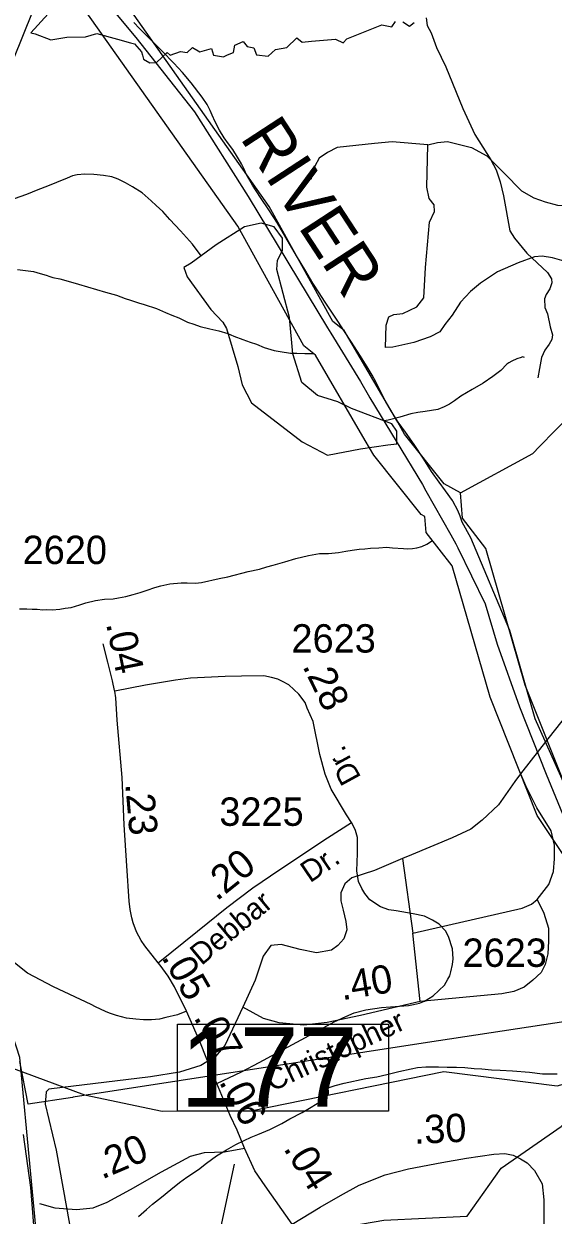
# Model space of a CAD drawing. Extents: x 2169602 to 2449496, y 721995 to 810662.
# Drawn here: x 2407514 to 2409846, y 768814 to 774064 of the extents above; entities that cross this region are included whole.
import ezdxf

# ---------------------------------------------------------------- set-up
doc = ezdxf.new("R2010")
doc.units = 0
doc.layers.add('Default', color=7, linetype='Continuous')

msp = doc.modelspace()

# ---------------------------------------------------------------- linework, layer by layer
at = {"layer": 'Default'}
for p, q in [((2409182, 770385.4), (2409227.4, 770056.2)), ((2409259.5, 769754.9), (2409227.4, 770056.2)), ((2407856.9, 766350.4), (2408442.4, 769038.3))]:
    msp.add_line(p, q, dxfattribs=at)
for points in [[(2407243.1, 773459.7), (2407266.6, 773555.6), (2407423.7, 773798.3), (2407554.7, 774123.7), (2407644.7, 774522.1), (2407675.7, 774915.1), (2407671.8, 775505.6), (2407762.6, 775631.7), (2407953.7, 775782), (2407976.7, 776132.5), (2408034.7, 776259.2), (2408241.6, 776425.6), (2408257.8, 776467.9)], [(2409161, 772308.5), (2408925.5, 772712.8), (2408875.4, 772752.6), (2408595.1, 773259.7), (2407918.3, 774218.5), (2407710.1, 774460.6), (2406974, 775062.6), (2406534.7, 775369.4), (2406337, 775427.8), (2406132.7, 775395.7), (2405988.4, 775292.7), (2405904.8, 775165.6), (2405866.1, 774953.6), (2405813.5, 774896.3), (2405664.8, 774846.1), (2405048.7, 774841.7), (2404832.6, 774882.2), (2404654.8, 774858.8), (2404509.3, 774858.8), (2404436.5, 774918.8), (2404333.7, 775051.5), (2404091.1, 775489.6), (2403987, 775680.8), (2403920.6, 775917.1)], [(2409017.8, 772228.4), (2408799.3, 772603.5), (2408747.7, 772644.5), (2408455.9, 773172.5), (2407788.9, 774117.5), (2407595.2, 774342.7), (2406875, 774931.7), (2406462.6, 775219.7), (2406326, 775260), (2406196.5, 775239.7), (2406108.7, 775177), (2406060.2, 775103.4), (2406019, 774877.5), (2405905.9, 774754.4), (2405688.3, 774680.8), (2404804.7, 774719.2), (2404466.4, 774709), (2404368, 774816), (2404234.3, 774963.9), (2403938.3, 775423.9), (2403840.1, 775854.6)], [(2407837.3, 774209.6), (2408006.5, 774004), (2408266.1, 773676), (2408501.7, 773303.2), (2408851.9, 772724.5), (2408866.1, 772701.4), (2408997.3, 772487.8), (2409030.9, 772429.7), (2409038.7, 772415.8), (2409270, 772034.6), (2409285, 772005.9), (2409395.5, 771811.6), (2409417.3, 771772.6), (2409425.7, 771755.2), (2409545.8, 771507.8), (2409599.8, 771329.8), (2409696.9, 771054.4), (2409815.7, 770757.6), (2409896.7, 770557.8)], [(2407665.9, 774158.4), (2407544.2, 774024.3), (2407563.7, 774019.7), (2407632.4, 773994.1), (2407702.9, 774005.5), (2407784.9, 774006.3), (2407835.9, 774022.2), (2407925.9, 773996), (2407983.9, 773980.4), (2408001.2, 773975.9), (2408032.4, 773940.3), (2408036.2, 773925.5), (2408040.7, 773908.6), (2408069.2, 773892.9), (2408098.7, 773893.6), (2408145.7, 773937.2), (2408158.2, 773925.6), (2408204.2, 773941.9), (2408233.9, 773937.6), (2408257.2, 773959.8), (2408288.9, 773941.1), (2408340.7, 773955.9), (2408348.7, 773925.9), (2408392.9, 773919.3), (2408411.2, 773927.1), (2408437.7, 773938.4), (2408443.2, 773969.8), (2408479.9, 773985.9), (2408497.7, 773964.3), (2408527.7, 773958.8), (2408538.4, 773928.2), (2408589.7, 773922.1), (2408622.2, 773951.6), (2408672.2, 773960.4), (2408716.7, 774002), (2408739.9, 773983.8), (2408780.7, 773987.5), (2408887.4, 773997.3), (2408919.9, 773979.8), (2408936.2, 773997.9), (2408959.4, 774007.2), (2409091.2, 774059.9), (2409135.2, 774051.4), (2409151.4, 774074.9)], [(2407665.9, 774158.4), (2407544.2, 774024.3), (2407563.7, 774019.7), (2407632.4, 773994.1), (2407702.9, 774005.5), (2407784.9, 774006.3), (2407835.9, 774022.2), (2407925.9, 773996), (2407983.9, 773980.4), (2408001.2, 773975.9), (2408032.4, 773940.3), (2408036.2, 773925.5), (2408040.7, 773908.6), (2408069.2, 773892.9), (2408098.7, 773893.6), (2408145.7, 773937.2), (2408158.2, 773925.6), (2408204.2, 773941.9), (2408233.9, 773937.6), (2408257.2, 773959.8), (2408288.9, 773941.1), (2408340.7, 773955.9), (2408348.7, 773925.9), (2408392.9, 773919.3), (2408411.2, 773927.1), (2408437.7, 773938.4), (2408443.2, 773969.8), (2408479.9, 773985.9), (2408497.7, 773964.3), (2408527.7, 773958.8), (2408538.4, 773928.2), (2408589.7, 773922.1), (2408622.2, 773951.6), (2408672.2, 773960.4), (2408716.7, 774002), (2408739.9, 773983.8), (2408780.7, 773987.5), (2408887.4, 773997.3), (2408919.9, 773979.8), (2408936.2, 773997.9), (2408959.4, 774007.2), (2409091.2, 774059.9), (2409135.2, 774051.4), (2409151.4, 774074.9)], [(2409930, 770637.4), (2409766.2, 771001.1), (2409655.2, 771391.1), (2409482.5, 771798.9), (2409445.2, 771867.8), (2409436, 771894.5), (2409426.5, 771919.3), (2409403.5, 771960.4), (2409402, 771962.9), (2409371.7, 772006.2), (2409343.2, 772044.1), (2409310.5, 772091.4), (2409275.5, 772145.9), (2409233.2, 772210.5), (2409195.7, 772264.4), (2409163.5, 772308.9), (2409133.2, 772355.3), (2409107.2, 772401.2), (2409083, 772447.6), (2409064, 772485.7), (2409048, 772515.7), (2409026.5, 772552.6), (2408997, 772599.7), (2408957.5, 772661.6), (2408927, 772708.1), (2408897, 772753.7), (2408868, 772797.4), (2408838.7, 772841.7), (2408814.5, 772878.5), (2408787.7, 772921.1), (2408755.7, 772974.3), (2408715.2, 773042.1), (2408667.7, 773122.6), (2408631, 773185.1), (2408593, 773245.2), (2408557, 773298.4), (2408521, 773352.9), (2408493.2, 773402.1), (2408483.7, 773423.1), (2408472.2, 773447.5), (2408455.7, 773476.8), (2408434, 773510.3), (2408415, 773535.9), (2408396.5, 773561.6), (2408375.5, 773596.1), (2408356.2, 773632), (2408343.2, 773661.6), (2408334.5, 773682.4), (2408320.7, 773708.1), (2408299.2, 773740.4), (2408251, 773804.6), (2408213, 773850.1), (2408174.5, 773891.2), (2408123.2, 773943.6), (2408069.2, 773997.9), (2408023.5, 774043.6), (2407998.5, 774069.7)], [(2409930, 770637.4), (2409766.2, 771001.1), (2409655.2, 771391.1), (2409482.5, 771798.9), (2409445.2, 771867.8), (2409436, 771894.5), (2409426.5, 771919.3), (2409403.5, 771960.4), (2409402, 771962.9), (2409371.7, 772006.2), (2409343.2, 772044.1), (2409310.5, 772091.4), (2409275.5, 772145.9), (2409233.2, 772210.5), (2409195.7, 772264.4), (2409163.5, 772308.9), (2409133.2, 772355.3), (2409107.2, 772401.2), (2409083, 772447.6), (2409064, 772485.7), (2409048, 772515.7), (2409026.5, 772552.6), (2408997, 772599.7), (2408957.5, 772661.6), (2408927, 772708.1), (2408897, 772753.7), (2408868, 772797.4), (2408838.7, 772841.7), (2408814.5, 772878.5), (2408787.7, 772921.1), (2408755.7, 772974.3), (2408715.2, 773042.1), (2408667.7, 773122.6), (2408631, 773185.1), (2408593, 773245.2), (2408557, 773298.4), (2408521, 773352.9), (2408493.2, 773402.1), (2408483.7, 773423.1), (2408472.2, 773447.5), (2408455.7, 773476.8), (2408434, 773510.3), (2408415, 773535.9), (2408396.5, 773561.6), (2408375.5, 773596.1), (2408356.2, 773632), (2408343.2, 773661.6), (2408334.5, 773682.4), (2408320.7, 773708.1), (2408299.2, 773740.4), (2408251, 773804.6), (2408213, 773850.1), (2408174.5, 773891.2), (2408123.2, 773943.6), (2408069.2, 773997.9), (2408023.5, 774043.6), (2407998.5, 774069.7)], [(2409183.7, 774072.7), (2409213.4, 774053.3), (2409233.7, 774069.9)], [(2409183.7, 774072.7), (2409213.4, 774053.3), (2409233.7, 774069.9)], [(2409285.9, 774090.9), (2409291.1, 774057.3), (2409307.9, 774025.1), (2409332.4, 773959.3), (2409372.4, 773874.1), (2409447.9, 773690.8), (2409500.8, 773575.9), (2409571.2, 773464.9), (2409594.4, 773421.1), (2409612.5, 773368.2), (2409626.7, 773306.2), (2409655.7, 773151.3), (2409675.1, 773120.3), (2409729.3, 773053.2), (2409821.5, 772968.1), (2409838.3, 772941), (2409839.6, 772922.9), (2409830.6, 772895.8), (2409815.1, 772871.3), (2409807.3, 772851.9), (2409809.9, 772814.5), (2409820.3, 772786.1), (2409832.5, 772729.3), (2409842.8, 772693.1), (2409840.3, 772672.5), (2409828.6, 772653.1), (2409809.3, 772626), (2409795.1, 772593.8), (2409786, 772544.7), (2409778.3, 772504.7)], [(2409294.1, 773531.4), (2409136, 773543.7), (2409059.4, 773536.3), (2408893.9, 773519), (2408852, 773496.8), (2408814.9, 773472.1), (2408795.2, 773437.5), (2408777.9, 773378.3)], [(2409107.6, 772637.3), (2409110.1, 772736.1), (2409122.4, 772773.1), (2409144.6, 772783), (2409184.2, 772787.9), (2409245.9, 772817.6), (2409275.5, 772857.1), (2409283, 772990.5), (2409301.5, 773190.5), (2409323.7, 773237.5), (2409321.2, 773267.1), (2409299, 773294.3), (2409289.1, 773343.7), (2409294.1, 773531.4)], [(2409294.1, 773531.4), (2409336.1, 773541.3), (2409380.5, 773546.2), (2409486.7, 773519), (2409553.4, 773482), (2409630, 773405.4), (2409706.6, 773328.9), (2409760.9, 773296.7), (2409810.3, 773279.5), (2409864.6, 773264.6), (2409926.4, 773262.2), (2410002.9, 773281.9), (2410069.6, 773294.3), (2410124, 773306.6), (2410185.7, 773311.6), (2410238.8, 773314)], [(2408294.6, 773042.1), (2408256.5, 773093.8), (2408204, 773151.7), (2408157.5, 773201.3), (2408125.7, 773237.3), (2408097.2, 773263.1), (2408075.3, 773284.7), (2408035.1, 773318.8), (2407992.8, 773346.2), (2407961.1, 773364), (2407928.9, 773379.8), (2407900.8, 773389.8), (2407864.7, 773395.6), (2407822.4, 773399.6), (2407782.7, 773401.1), (2407748.8, 773398.9), (2407728.5, 773394.7), (2407704.7, 773384.5), (2407656.8, 773364.6), (2407617.2, 773348.3), (2407574.9, 773331.9), (2407525.1, 773311.9), (2407471.2, 773293.3)], [(2409785.9, 772200.8), (2410062.6, 772482.8), (2410419.6, 772734.6), (2410494.4, 772834.8), (2410484.6, 773008.8), (2410375.5, 773152.2), (2410283.4, 773199.9), (2410241.6, 773276.3), (2410258.9, 773346.9)], [(2408360.9, 773090.4), (2408250.5, 773009.9), (2408217.9, 772989.8), (2408232.9, 772949.7), (2408338.2, 772804.5), (2408390.8, 772749.4), (2408405.9, 772721.8), (2408456.2, 772554.1), (2408476.1, 772473.9), (2408516.2, 772393.7), (2408739.6, 772221.9), (2408852, 772163.3), (2408997.4, 772190.8), (2409117.7, 772208.4), (2409157.8, 772213.4), (2409157.8, 772268.5), (2409135.3, 772301.1), (2408957.3, 772368.7), (2408897.6, 772398.9), (2408806.9, 772426.3), (2408739.2, 772483.9), (2408699.1, 772609.1), (2408684.1, 772769.4), (2408627.9, 772981.5), (2408631.5, 773022.4), (2408654, 773065), (2408654, 773120.1), (2408616.4, 773170.2), (2408558.8, 773185.2), (2408486.1, 773170.2), (2408360.9, 773090.4)], [(2410317.9, 773064.6), (2410136.3, 773017.6), (2410086.9, 772997.9), (2410035, 772990.5), (2409990.6, 772990.5), (2409953.5, 772997.9), (2409894.3, 773017.6), (2409842.4, 773032.5), (2409797.9, 773039.9), (2409763.4, 773037.4), (2409691.7, 773010.2), (2409600.3, 772970.7), (2409526.2, 772921.3), (2409481.8, 772884.3), (2409437.3, 772837.3), (2409400.3, 772780.5), (2409368.2, 772738.5), (2409345.9, 772706.4), (2409304, 772684.2), (2409232.3, 772659.5), (2409139.7, 772639.7), (2409107.6, 772637.3)], [(2407485.7, 772981.6), (2407521.1, 772977.8), (2407555.4, 772972.2), (2407585.1, 772964.5), (2407611.6, 772956.4), (2407627.6, 772950.4), (2407641.7, 772946.6), (2407671.9, 772940.9), (2407699.3, 772933), (2407753.7, 772917.1), (2407873.6, 772882), (2407921.8, 772868.2), (2407960, 772854.3), (2407983.7, 772846.6), (2408018.4, 772834.9), (2408043.8, 772827), (2408098.4, 772809.4), (2408138.1, 772791.6), (2408166.4, 772779.7), (2408196.4, 772767.8), (2408234.1, 772750), (2408262.4, 772740.4), (2408290.5, 772730.5), (2408332.5, 772720.5), (2408372.5, 772710.8), (2408412.7, 772699), (2408438.7, 772687), (2408478.9, 772673.6), (2408510.9, 772661.5), (2408538.6, 772652), (2408572.9, 772637.9), (2408616.9, 772624.4), (2408642.8, 772620.5), (2408688.9, 772612.7), (2408717, 772612.9), (2408751.2, 772610.9), (2408789.9, 772611)], [(2409720.2, 772594.3), (2409710.4, 772596.2), (2409704.6, 772594.3), (2409686.6, 772588.1), (2409664.4, 772578), (2409650.7, 772569.9), (2409642.5, 772563.9), (2409615, 772536), (2409580.8, 772509.5), (2409537.3, 772481.2), (2409489.3, 772453.2), (2409439.7, 772422.9), (2409411.6, 772402.9), (2409389.9, 772388.7), (2409365.7, 772376.6), (2409338.2, 772364.1), (2409310.3, 772360.2), (2409282, 772355.9), (2409250.2, 772351.8), (2409218.2, 772345.7), (2409170.2, 772331.4), (2409118.2, 772317), (2409101.3, 772313.9)], [(2409437.5, 771997.1), (2409366.4, 772037.6), (2409191.3, 772256.5), (2409161, 772308.5)], [(2409279.9, 771892.5), (2409264.7, 771902.1), (2409055.6, 772163.5), (2409017.8, 772228.4)], [(2409437.5, 771997.1), (2409756.4, 772170.8), (2409785.9, 772200.8)], [(2410451.8, 769576.3), (2410433.4, 769734.9), (2410163.8, 770289.2), (2409921.5, 770652.4), (2409723.2, 771150), (2409550, 771752), (2409445.9, 771885.5), (2409437.5, 771997.1)], [(2410288.9, 769557.4), (2410273.7, 769688.2), (2410021.2, 770207.4), (2409775.5, 770575.7), (2409567.8, 771096.8), (2409401.1, 771676.2), (2409286.9, 771822.6), (2409279.9, 771892.5)], [(2407787.3, 771511.8), (2407829.5, 771522.1), (2407869.1, 771528.3), (2407907.5, 771530.6), (2407931, 771534.7), (2407963.4, 771540.8), (2407995, 771549), (2408025.4, 771557.4), (2408057.1, 771567.6), (2408091, 771579.5), (2408116.6, 771587.8), (2408156.6, 771595.9), (2408206.6, 771600.1), (2408232.7, 771600.3), (2408270.6, 771598.6), (2408296.9, 771602.7), (2408374.8, 771619.3), (2408412.7, 771627.4), (2408502.7, 771649.9), (2408552.6, 771660.2), (2408584.3, 771670.4), (2408612.4, 771678.4), (2408664.1, 771692.8), (2408712.1, 771707.1), (2408767.9, 771721.4), (2408816, 771729.5), (2408855.6, 771730), (2408900.1, 771734.2), (2408931.7, 771740.4), (2408959.6, 771744.7), (2408991.8, 771748.7), (2409016, 771750.8), (2409041.8, 771752.9), (2409077.9, 771755.2), (2409111.3, 771757.4), (2409137.4, 771755.5), (2409185.8, 771751.9), (2409205.6, 771749.7), (2409225.5, 771751.9), (2409245.6, 771754.2), (2409267.4, 771760.2), (2409289.5, 771770.3), (2409314.5, 771787.2)], [(2407593.3, 768488.6), (2407969.6, 768561.8), (2408193.6, 768635.9), (2409100.5, 768791.2), (2409467.6, 768810), (2409616.6, 769020.2), (2409881.5, 769205), (2410196.5, 769523.3), (2410328.6, 769730.6), (2410592.5, 770233.6), (2410766.6, 770341.6), (2411514.6, 770644.5), (2411995.6, 771074.3), (2412234.5, 771423.7), (2412358.6, 771726.2)], [(2407493.7, 771486.5), (2407526.1, 771486.4), (2407549.8, 771484.5), (2407571.6, 771484.8), (2407597.8, 771480.9), (2407611.8, 771482.8), (2407637.8, 771481.3), (2407671.6, 771485.1), (2407695.6, 771489.6), (2407721.5, 771491.8), (2407759.6, 771503.9), (2407787.3, 771511.8)], [(2410196.8, 771469), (2410100.5, 771367.7), (2409996.8, 771286.2), (2409977, 771246.7), (2409977, 771212.1), (2409979.5, 771165.2), (2409972.1, 771120.7), (2409959.7, 771091.1), (2409940, 771061.5), (2409822.6, 770913.3), (2409702.2, 770758.2)], [(2407913.9, 771123.6), (2407913.3, 771126.4), (2407904.2, 771168.1), (2407883, 771250.7), (2407863.7, 771331.1)], [(2408956.8, 770544.9), (2408935.3, 770578.7), (2408867.3, 770691.5), (2408842, 770757.2), (2408818.4, 770843.7), (2408788.5, 770989), (2408762.3, 771048.4), (2408753.2, 771072.8), (2408726, 771109.5), (2408681.2, 771150.7), (2408653.6, 771165.2), (2408632.3, 771175.6), (2408604.7, 771183.8), (2408571.6, 771190.1), (2408472.4, 771188.8), (2408400, 771187.9), (2408309.4, 771183.8), (2408247.3, 771179.7), (2408181.7, 771171.1), (2408049.4, 771148.9), (2407913.9, 771123.6)], [(2408105.4, 769926.1), (2408047.1, 770000.5), (2408030.4, 770024.4), (2408010, 770062.3), (2407995, 770102.5), (2407988.7, 770124.1), (2407982.5, 770160.4), (2407977.4, 770197.6), (2407966.8, 770353.7), (2407955.4, 770534.5), (2407946.3, 770742.2), (2407925.4, 770994.6), (2407919, 771094.1), (2407913.9, 771123.6)], [(2409702.2, 770758.2), (2409676.9, 770725.6), (2409605.3, 770621.8), (2409532.4, 770555.1), (2409483, 770515.6), (2409401.5, 770476.1), (2409221.2, 770402), (2409182, 770385.4)], [(2409775.7, 770204.4), (2409827.6, 770271.1), (2409847.3, 770327.9), (2409852.3, 770384.7), (2409852.3, 770444), (2409837.5, 770508.2), (2409774.5, 770609.5), (2409725.1, 770705.8), (2409702.8, 770757.7)], [(2408105.4, 769926.1), (2408278.8, 770065.4), (2408408.7, 770170.2), (2408522.9, 770255.9), (2408642.1, 770337.6), (2408851.3, 770476.6), (2408956.8, 770544.9)], [(2408364.4, 769393.5), (2408472.5, 769444.8), (2408550.8, 769486.4), (2408789.3, 769616), (2408881.7, 769666), (2408932.2, 769689.9), (2408968.9, 769705.8), (2409020.2, 769719.1), (2409089, 769728.3), (2409207.8, 769738.1), (2409230.8, 769741.7), (2409256.9, 769747.4), (2409279, 769757.2), (2409316.6, 769779.7), (2409367, 769827.9), (2409382.5, 769853.6), (2409390, 769868.6), (2409395.3, 769886.3), (2409402.4, 769918.6), (2409405.1, 769943), (2409402.9, 769987.2), (2409384.3, 770042.5), (2409371.5, 770066.8), (2409344, 770096.5), (2409313.9, 770114.2), (2409279, 770131.4), (2409229, 770141.6), (2409154.2, 770154.4), (2409121.5, 770159.3), (2409085.2, 770172.5), (2409038.5, 770203.8), (2409015.4, 770231.8), (2409002.3, 770254), (2408987.6, 770284), (2408980.3, 770331.5), (2408983.3, 770407.6), (2408984.2, 770459.2), (2408983.7, 770477.7), (2408975.6, 770509), (2408958.4, 770542.5), (2408956.8, 770544.9)], [(2409182, 770385.4), (2409058.2, 770332.8), (2408959.4, 770300.7), (2408927.3, 770273.6), (2408910, 770234), (2408910, 770199.5), (2408919.9, 770157.5), (2408932.2, 770108.1), (2408937.2, 770071), (2408923.6, 770031.5), (2408896.4, 770001.9), (2408869.2, 769982.1), (2408802.6, 769969.8), (2408730.9, 769984.6), (2408647, 770006.8), (2408602.5, 770001.9), (2408567.9, 769954.9), (2408533.3, 769848.7), (2408479, 769730.2)], [(2409227.4, 770056.2), (2409709, 770167.4), (2409751, 770184.6), (2409775.7, 770204.4)], [(2409775.7, 770204.4), (2409805.3, 770145.1), (2409825.1, 770078.4), (2409825.1, 770021.6), (2409822.6, 769964.8), (2409810.3, 769917.9), (2409793, 769883.3), (2409755.9, 769848.7), (2409718.9, 769819.1), (2409672, 769799.3), (2409620.1, 769789.5), (2409259.5, 769754.9)], [(2408231, 769712.2), (2408190.1, 769696.9), (2408139.1, 769684.8), (2408111.9, 769678.2), (2408076, 769675.2), (2408040.5, 769674.9), (2408007.1, 769677), (2407965.6, 769682.1), (2407921.6, 769693.6), (2407891.3, 769704.2), (2407873.6, 769710.7), (2407829.5, 769732.1), (2407809.9, 769742), (2407644.7, 769819.6), (2407529.1, 769880.7), (2407472.2, 769926.1)], [(2408231, 769712.2), (2408177.8, 769820), (2408149.5, 769866.7), (2408114.1, 769914.9), (2408105.4, 769926.1)], [(2409259.5, 769754.9), (2408996.4, 769693.1), (2408850.7, 769663.5), (2408747, 769651.1), (2408638.3, 769661), (2408569.2, 769680.8), (2408479, 769730.2)], [(2407593.2, 768480.4), (2407495.4, 769508), (2407432.6, 769704.6)], [(2408479, 769730.2), (2408398.7, 769562.2), (2408358, 769512.8), (2408293.8, 769473.3), (2408199.9, 769443.7), (2408071.5, 769423.9), (2407624.4, 769369.6), (2407612.1, 769357.2), (2407607.1, 769302.9), (2407656.5, 769100.4), (2407714.6, 768774.3), (2407726.9, 768660.7), (2407724.4, 768591.5), (2407719.5, 768507.6), (2407703.4, 768164.3), (2407681.2, 767919.7), (2407665.2, 767670.3), (2407641.7, 767163.9), (2407655.3, 766860.1), (2407657.8, 766578.6), (2407693.6, 766279.7), (2407705.9, 766188.3), (2407733.1, 766096.9), (2407803.5, 765919.1)], [(2408364.4, 769393.5), (2408320.3, 769501.9), (2408288.8, 769579.3), (2408231, 769712.2)], [(2405398.5, 767831.3), (2405736.4, 768441.1), (2406472.5, 769564.4), (2406605.4, 769630.5), (2407113.5, 769590.7), (2407781.4, 769344.2), (2408123.4, 769271.5), (2408514.4, 769273.4), (2409363.5, 769446.4), (2409863.4, 769383.7), (2410304.2, 769504.3)], [(2409920.2, 769670.6), (2409273.7, 769571.1), (2407949.7, 769367.1), (2407730.7, 769333.4), (2407728.4, 769333), (2407533.2, 769303), (2407496.2, 769490.8)], [(2409920.2, 769670.6), (2409273.7, 769571.1), (2407949.7, 769367.1), (2407730.7, 769333.4), (2407728.4, 769333), (2407533.2, 769303), (2407496.2, 769490.8)], [(2408854.8, 769374.7), (2408884.9, 769384.7), (2408925.3, 769394.9), (2409020.9, 769415.7), (2409068.7, 769423.9), (2409113, 769434.3), (2409166.3, 769446.5), (2409220.6, 769458.5), (2409248.5, 769464.9), (2409284.6, 769467.1), (2409340.8, 769467.5), (2409378.3, 769465.5), (2409420.3, 769466), (2409456.2, 769463.9), (2409498, 769460.4), (2409532.1, 769458.5), (2409574.5, 769454.9), (2409612.5, 769452.8), (2409666.2, 769449.2), (2409742.3, 769443.7), (2409798.7, 769436), (2409864.3, 769436.3)], [(2408018.4, 768808.4), (2408054.5, 768838.2), (2408080.1, 768862.7), (2408120.1, 768892.8), (2408161.9, 768927), (2408200.1, 768957), (2408231.6, 768981.4), (2408283.3, 769015.7), (2408319, 769043.6), (2408363.1, 769075.9), (2408407, 769102.1), (2408448.4, 769124.6), (2408484.7, 769142.7), (2408514.6, 769156.8), (2408544.3, 769169), (2408598.1, 769191.2), (2408650.2, 769217.5), (2408686.2, 769237.6), (2408739.8, 769266), (2408779.5, 769290.4), (2408817.7, 769312.6), (2408837.4, 769328.7), (2408849.1, 769340.7), (2408855.6, 769348.7), (2408855.6, 769356.8), (2408854.8, 769374.7)], [(2408485.4, 769109.5), (2408453.6, 769188.7), (2408423, 769252.3), (2408364.4, 769393.5)], [(2407510.8, 769169.2), (2407542.7, 768935.6), (2407558.9, 768733.2)], [(2407582, 768864.5), (2407650.4, 768845.7), (2407745.4, 768838.9), (2407818.9, 768845.7), (2407880.5, 768871.3), (2407983.1, 768926.1), (2408120, 769004.8), (2408248.3, 769073.2), (2408309.8, 769090.3), (2408398.2, 769093.2), (2408485.4, 769109.5)], [(2408696.3, 768774.2), (2408576.2, 768943.5), (2408531.6, 769009.5), (2408485.4, 769109.5)], [(2408696.3, 768774.2), (2408819.4, 768849.2), (2408908.3, 768900.5), (2408991.5, 768946), (2409106.1, 768991.1), (2409208.7, 769018.5), (2409355.8, 769045.8), (2409463.9, 769064.9), (2409584.4, 769083), (2409632.3, 769085.5), (2409670.3, 769078.1), (2409702.5, 769062.4), (2409731.4, 769045), (2409763.6, 769011.2), (2409797.5, 768951.7), (2409804.5, 768881.5), (2409804.5, 768767.6), (2409802, 768652)]]:
    msp.add_lwpolyline(points, dxfattribs=at)
msp.add_lwpolyline([(2408190.8, 769656.2), (2409119.7, 769656.2), (2409119.7, 769272), (2408190.8, 769272)], close=True, dxfattribs=at)

# ---------------------------------------------------------------- texts
for s, height, rotation, p in [('RIVER', 210, 303.1395, (2408463.2, 773562.4)), ('.04', 125, 281.49, (2407875.4, 771420.3)), ('.28', 125, 295.8765, (2408739.6, 771234)), ('Dr.', 95, 118.583, (2409001.7, 770742.6)), ('.23', 125, 275.0612, (2407960.1, 770714.7)), ('.20', 125, 38.7317, (2408363.5, 770195.4)), ('Dr.', 95, 34.1552, (2408774.4, 770276)), ('Debbar', 95, 39.7209, (2408296, 769911.3)), ('.05', 125, 299.9249, (2408118.5, 769950.2)), ('.40', 125, 9.3005, (2408916.2, 769760.4)), ('.07', 125, 299.9249, (2408259.7, 769684.9)), ('Christopher', 95, 25.2344, (2408607.3, 769356.7)), ('.06', 125, 298.0343, (2408371.5, 769402.1)), ('.30', 125, 2.4088, (2409234.1, 769127.8)), ('.20', 125, 23.0962, (2407857.8, 768970.2)), ('.04', 125, 301.7189, (2408655.1, 769107.7))]:
    msp.add_text(s, height=height, rotation=rotation, dxfattribs=at).set_placement(p)
for s, height, p in [('2620', 125, (2407508.1, 771683.3)), ('2623', 125, (2408692.7, 771293.2)), ('3225', 125, (2408375, 770529.6)), ('2623', 125, (2409446.5, 769908)), ('177', 350, (2408203.3, 769291.8))]:
    msp.add_text(s, height=height, dxfattribs=at).set_placement(p)

doc.saveas('drawing.dxf')
